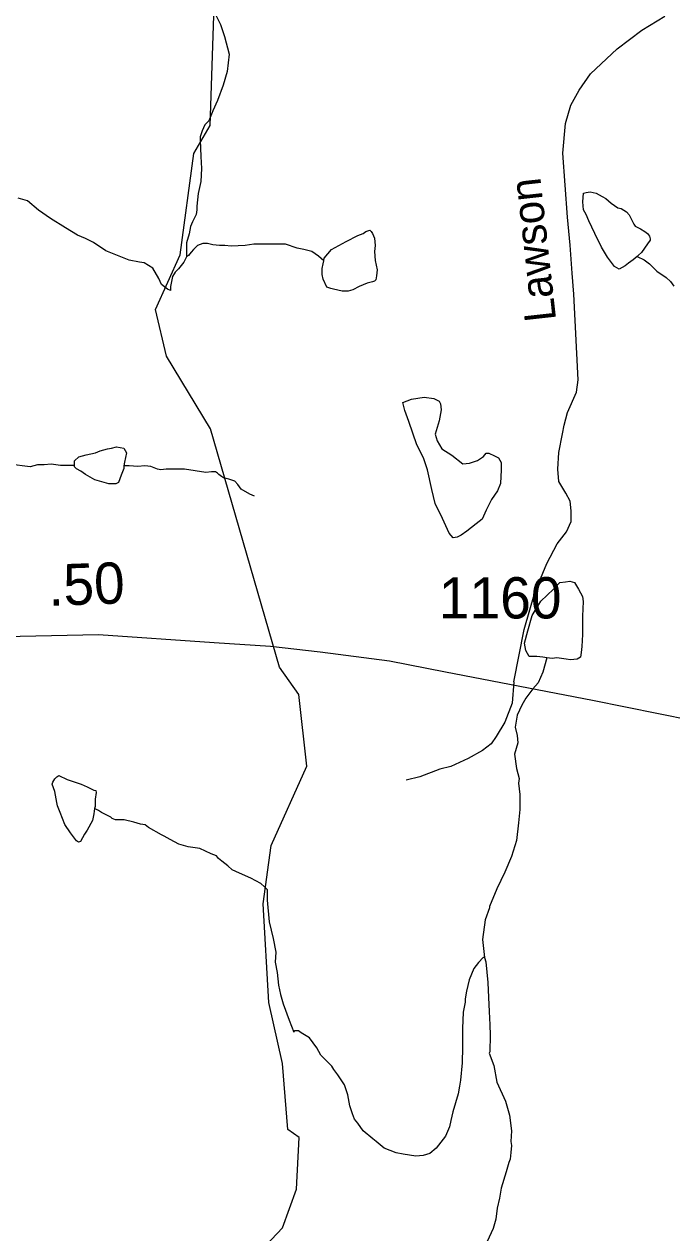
# Model space of a CAD drawing. Extents: x 2001466 to 2224147, y 644118 to 847247.
# Drawn here: x 2016789 to 2018752, y 719190 to 722853 of the extents above; entities that cross this region are included whole.
import ezdxf

# ---------------------------------------------------------------- set-up
doc = ezdxf.new("R2010")
doc.units = 0
for name, color, linetype in [('Exist Hydrographic Misc Water Feature', 7, 'Continuous'), ('Exist Road Non-System Type 51', 7, 'Continuous'), ('Exist Road Non-System Type 51 Label', 7, 'Continuous'), ('Exist Road Secondary Mileage Hundredths English Label', 7, 'Continuous'), ('Exist Road Secondary Type 51 Attributed', 7, 'Continuous'), ('Exist Road Secondary Type 51 Number Label', 7, 'Continuous')]:
    doc.layers.add(name, color=color, linetype=linetype)

msp = doc.modelspace()

# ---------------------------------------------------------------- linework, layer by layer
at = {"layer": 'Exist Hydrographic Misc Water Feature'}
msp.add_line((2017588.2, 719502.9), (2017572.2, 719703.4), dxfattribs=at)
for points in [[(2017572.2, 719703.4), (2017530.2, 719888), (2017513.2, 720187), (2017538.2, 720363.7), (2017646.3, 720604.2), (2017621.3, 720821.3), (2017563.2, 720904.5), (2017354.3, 721627.3), (2017220.2, 721846.6), (2017187.2, 721988.4), (2017262.2, 722154.2), (2017303.2, 722461.7), (2017353.2, 722546.1), (2017370.3, 723060.9), (2017878.4, 724028.3), (2017977.2, 724180.4), (2018152.3, 724528), (2018185.4, 724694.7)], [(2017370.5, 722880.2), (2017384.4, 722852.1), (2017396.5, 722816.1), (2017410.5, 722762.1), (2017404.5, 722710.1), (2017392.6, 722668.1), (2017374.6, 722622.2), (2017360.6, 722590.1), (2017348.5, 722560.1), (2017336.6, 722548.1), (2017328.6, 722530.1), (2017322.7, 722512.1), (2017322.7, 722502.1), (2017324.7, 722452.1), (2017326.8, 722416.1), (2017324.7, 722376.1), (2017316.7, 722340.2), (2017312.6, 722302.1), (2017312.6, 722290.1), (2017310.8, 722276.1), (2017298.9, 722254.1), (2017293, 722240.1), (2017288.9, 722218.1), (2017280.9, 722190.2), (2017280.9, 722160.1), (2017280.9, 722148.1)], [(2018646.7, 722148.9), (2018634.8, 722138.9), (2018620.7, 722128.9), (2018610.6, 722120.9), (2018592.8, 722110.9), (2018578.6, 722118.9), (2018556.7, 722146.9), (2018538.7, 722176.9), (2018518.8, 722218.8), (2018500.5, 722256.9), (2018492.5, 722276.8), (2018484.5, 722290.8), (2018482.7, 722314.8), (2018484.5, 722340.8), (2018492.5, 722342.8), (2018504.6, 722344.8), (2018522.7, 722340.8), (2018540.7, 722330.8), (2018552.6, 722324.8), (2018568.6, 722310.9), (2018588.7, 722296.9), (2018598.5, 722294.9), (2018614.5, 722284.9), (2018622.5, 722274.9), (2018636.7, 722247), (2018640.6, 722240.9), (2018656.8, 722233), (2018670.5, 722225), (2018678.7, 722219), (2018684.7, 722211), (2018686.7, 722203), (2018686.7, 722199), (2018678.5, 722187), (2018660.7, 722161), (2018650.8, 722152.9), (2018646.7, 722148.9)], [(2017232.9, 722046.1), (2017223, 722050.1), (2017205, 722064), (2017196.8, 722082.1), (2017179, 722114.1), (2017152.9, 722130.1), (2017138.8, 722132.1), (2017106.8, 722138.1), (2017036.9, 722166), (2016998.9, 722192), (2016974.9, 722203.9), (2016950.9, 722213.9), (2016914.8, 722235.9), (2016868.9, 722263.9), (2016832.8, 722289.9), (2016798.8, 722317.8), (2016770.9, 722325.8)], [(2017696.9, 722136.4), (2017698.8, 722144.4), (2017720.9, 722170.4), (2017764.8, 722194.5), (2017800.7, 722212.5), (2017816.7, 722218.5), (2017824.7, 722224.5), (2017836.8, 722228.5), (2017840.7, 722224.5), (2017844.8, 722218.5), (2017850.7, 722204.5), (2017852.8, 722182.5), (2017850.9, 722164.5), (2017852.8, 722136.5), (2017858.9, 722108.4), (2017856.9, 722090.5), (2017854.8, 722078.5), (2017850.9, 722074.5), (2017844.8, 722072.5), (2017828.8, 722068.5), (2017804.8, 722058.5), (2017784.9, 722048.5), (2017770.9, 722044.5), (2017752.9, 722044.5), (2017726.9, 722050.4), (2017718.9, 722052.4), (2017706.8, 722056.4), (2017694.9, 722080.4), (2017692.8, 722094.4), (2017692.8, 722112.4), (2017694.9, 722126.4), (2017696.9, 722136.4)], [(2017696.9, 722136.4), (2017680.9, 722150.4), (2017660.8, 722164.4), (2017636.8, 722170.4), (2017616.9, 722174.3), (2017580.9, 722186.3), (2017542.9, 722186.3), (2017502.9, 722186.3), (2017484.9, 722186.3), (2017458.9, 722182.2), (2017416.8, 722180.3), (2017396.9, 722182.2), (2017380.9, 722182.2), (2017360.8, 722184.2), (2017344.8, 722188.2), (2017330.9, 722188.2), (2017314.9, 722182.1), (2017302.8, 722170.1), (2017294.8, 722162.1), (2017286.8, 722152.1), (2017280.9, 722148.1)], [(2017280.9, 722148.1), (2017272.9, 722132.1), (2017256.9, 722112.1), (2017246.8, 722102.1), (2017238.8, 722088.1), (2017232.9, 722058.2), (2017232.9, 722046.1)], [(2018646.7, 722148.9), (2018668.7, 722138.9), (2018684.7, 722126.9), (2018706.8, 722105), (2018734.7, 722085), (2018748.6, 722073), (2018758.7, 722059)], [(2017955.1, 721648.6), (2017943.2, 721682.6), (2017937, 721706.6), (2017962.9, 721716.6), (2018001, 721722.6), (2018030.9, 721718.6), (2018047.1, 721710.6), (2018051, 721702.6), (2018053.1, 721684.7), (2018047.1, 721650.7), (2018035, 721610.6), (2018041, 721590.6), (2018055.1, 721566.6), (2018085.1, 721546.7), (2018119.1, 721520.7), (2018139, 721522.7), (2018163, 721530.8), (2018181, 721542.8), (2018189, 721552.8), (2018197, 721552.8), (2018215.1, 721544.8), (2018227.2, 721538.8), (2018235.2, 721524.8), (2018235.2, 721502.8), (2018233.1, 721460.8), (2018223.3, 721438.8), (2018205.2, 721412.8), (2018189.2, 721380.8), (2018177.1, 721352.8), (2018159.3, 721338.8), (2018131.2, 721316.8), (2018113.2, 721304.7), (2018101.3, 721298.7), (2018089.2, 721296.7), (2018077.3, 721310.7), (2018057.2, 721354.7), (2018035.3, 721400.7), (2018025.2, 721442.6), (2018011.1, 721502.6), (2017999.2, 721538.7), (2017979.1, 721578.6), (2017955.1, 721648.6)], [(2016941.3, 721516), (2016921.2, 721516), (2016899.3, 721516), (2016871.2, 721519.9), (2016849.2, 721517.9), (2016837.3, 721517.9), (2016829.3, 721517.9), (2016807.2, 721511.9), (2016743.4, 721519.9), (2016677.4, 721529.9), (2016621.4, 721541.8), (2016579.2, 721563.8), (2016523.2, 721571.7), (2016495.3, 721577.7), (2016475.4, 721585.8), (2016449.4, 721583.8), (2016439.3, 721579.7), (2016407.3, 721577.7), (2016383.4, 721573.7), (2016359.4, 721569.7), (2016343.4, 721565.6), (2016331.3, 721553.6), (2016319.4, 721545.7)], [(2016941.3, 721516), (2016941.3, 721522), (2016941.3, 721530), (2016955.2, 721542), (2016977.2, 721548), (2017005.3, 721554.1), (2017019.2, 721560.1), (2017041.2, 721566.1), (2017053.3, 721568.1), (2017069.3, 721572.1), (2017091.2, 721568.1), (2017099.2, 721554.1), (2017093.2, 721526.1), (2017091.2, 721514.2)], [(2017091.2, 721514.2), (2017091.2, 721506.1), (2017083.2, 721486.1), (2017075.4, 721464.1), (2017067.2, 721460.1), (2017045.3, 721460.1), (2017003.4, 721472.1), (2016975.1, 721488.1), (2016961.2, 721498), (2016947.2, 721506), (2016941.3, 721512), (2016941.3, 721516)], [(2017487.1, 721422.4), (2017473.2, 721428.3), (2017447.2, 721444.3), (2017437.1, 721458.3), (2017427.3, 721468.3), (2017409.2, 721474.3), (2017393.2, 721478.3), (2017387.3, 721482.3), (2017379.3, 721488.3), (2017375.2, 721492.3), (2017369.2, 721496.3), (2017357.1, 721496.3), (2017339.3, 721494.3), (2017275.1, 721504.2), (2017237.2, 721504.2), (2017219.1, 721504.2), (2017203.2, 721502.2), (2017193.3, 721504.1), (2017173.2, 721512.2), (2017155.2, 721514.2), (2017133.2, 721512.2), (2017107.2, 721514.2), (2017091.2, 721514.2)], [(2018373.4, 720933), (2018361.5, 720934.9), (2018343.4, 720936.9), (2018329.5, 720936.9), (2018319.5, 720936.9), (2018309.4, 720954.9), (2018305.5, 720976.9), (2018315.4, 721014.9), (2018329.3, 721060.9), (2018355.3, 721104.9), (2018393.3, 721140.9), (2018413.2, 721160.9), (2018429.4, 721162.9), (2018443.3, 721164.9), (2018457.2, 721160.9), (2018469.3, 721141), (2018481.2, 721119), (2018483.3, 721103), (2018481.2, 721058.9), (2018481.2, 721028.9), (2018481.2, 721003), (2018479.4, 720967), (2018477.3, 720949), (2018475.5, 720935), (2018465.5, 720929), (2018445.4, 720927), (2018431.4, 720929), (2018403.5, 720933), (2018389.4, 720931), (2018373.4, 720933)], [(2018373.4, 720933), (2018361.5, 720888.9), (2018347.3, 720856.9), (2018331.3, 720839), (2018309.4, 720810.9), (2018297.5, 720788.9), (2018283.6, 720758.9), (2018277.6, 720722.9), (2018283.6, 720696.9), (2018285.6, 720674.9), (2018275.6, 720640.9), (2018281.5, 720596.9), (2018289.5, 720566.9), (2018287.5, 720552.9), (2018291.8, 720518.9), (2018291.8, 720472.9), (2018287.7, 720433), (2018281.7, 720378.9), (2018265.7, 720330.9), (2018245.8, 720282.9), (2018221.8, 720232.9), (2018199.7, 720178.9), (2018199.7, 720174.9), (2018186, 720138.9), (2018178, 720078.9), (2018181.9, 720042.9), (2018183.9, 720025)], [(2017001.8, 720476.2), (2016999.7, 720460.2), (2016995.8, 720440.2), (2016979.8, 720410.2), (2016971.9, 720398.2), (2016960, 720376.2), (2016954, 720374.1), (2016947.9, 720378.1), (2016929.8, 720402.1), (2016911.8, 720428.1), (2016897.8, 720464.1), (2016889.8, 720484.1), (2016887.8, 720494.1), (2016881.8, 720528.1), (2016873.8, 720550), (2016875.9, 720556), (2016881.8, 720566), (2016887.8, 720572.1), (2016893.7, 720576), (2016919.8, 720564.1), (2016961.8, 720550.1), (2016979.8, 720542.1), (2016999.7, 720532.1), (2017005.9, 720530.2), (2017007.7, 720524.2), (2017003.8, 720504.2), (2017003.8, 720482.2), (2017001.8, 720476.2)], [(2017525.9, 720230.5), (2017517.9, 720238.5), (2017506, 720248.5), (2017475.9, 720264.5), (2017441.8, 720280.5), (2017419.9, 720290.5), (2017405.9, 720302.4), (2017387.9, 720316.4), (2017377.9, 720324.4), (2017371.9, 720332.4), (2017355.7, 720338.4), (2017321.9, 720354.4), (2017285.8, 720360.4), (2017257.9, 720368.4), (2017231.9, 720382.3), (2017213.8, 720392.3), (2017205.8, 720396.3), (2017165.8, 720418.3), (2017155.8, 720426.2), (2017141.8, 720428.2), (2017121.7, 720434.2), (2017091.8, 720442.2), (2017065.8, 720442.2), (2017055.7, 720446.2), (2017051.8, 720450.2), (2017043.8, 720454.2), (2017035.8, 720458.2), (2017023.7, 720464.2), (2017013.9, 720470.2), (2017001.8, 720476.2)], [(2017525.9, 720230.5), (2017525.9, 720198.5), (2017531.8, 720132.5), (2017543.9, 720082.5), (2017551.9, 720040.5), (2017550.1, 720010.6), (2017556, 719978.6), (2017560.1, 719940.6), (2017566.1, 719912.6), (2017574.1, 719884.6), (2017592.1, 719834.6), (2017606.1, 719798.6)], [(2018183.9, 720025), (2018180, 720024.9), (2018165.9, 720009), (2018151.9, 719990.9), (2018138, 719956.9), (2018130, 719922.9), (2018126.1, 719898.9), (2018126.1, 719888.9), (2018124, 719878.9), (2018119.9, 719858.9), (2018118.1, 719808.9), (2018118.1, 719774.9), (2018118.1, 719742.9), (2018116.2, 719715), (2018116.2, 719704.9), (2018112.1, 719652.9), (2018108.3, 719635), (2018104.1, 719611), (2018088.2, 719556.9), (2018082.2, 719530.9), (2018078.1, 719510.9), (2018066.2, 719483), (2018052.3, 719464.9), (2018038.3, 719446.9), (2018018.2, 719430.9), (2017998.3, 719424.9), (2017976.2, 719422.9), (2017938.3, 719428.8), (2017916.3, 719432.8), (2017880.2, 719446.8), (2017856.2, 719466.8), (2017846.2, 719474.8), (2017816.3, 719498.7), (2017800.3, 719522.7), (2017790.2, 719534.7), (2017784.3, 719550.8), (2017776.1, 719574.8), (2017770.1, 719608.7), (2017760.1, 719638.7), (2017740.2, 719668.7), (2017728.1, 719684.7), (2017722.1, 719694.7), (2017706.1, 719710.7), (2017700.2, 719716.7), (2017688.1, 719728.7), (2017676.2, 719750.7), (2017654.3, 719780.6), (2017628.2, 719796.6), (2017620.2, 719802.6), (2017608.1, 719802.6), (2017606.1, 719798.6)], [(2018183.9, 720025), (2018188, 720011), (2018194, 719948.9), (2018196, 719903), (2018198.1, 719861), (2018200.1, 719820.9), (2018202, 719788.9), (2018200.1, 719739), (2018198.1, 719735), (2018212.2, 719696.9), (2018222.1, 719647), (2018248.1, 719589), (2018260.2, 719547), (2018266.1, 719499), (2018264.1, 719467), (2018266.3, 719455), (2018264.3, 719433.1), (2018262.2, 719413), (2018258.3, 719403.1), (2018250.4, 719375), (2018234.4, 719325), (2018230.3, 719295.1), (2018222.5, 719265), (2018218.4, 719231.1), (2018210.4, 719203), (2018186.4, 719151)], [(2016839.2, 718238.5), (2016997.1, 718304.3), (2017106.2, 718420.2), (2017422.1, 719047), (2017572.2, 719204.7), (2017614.1, 719321.9), (2017622.1, 719479.3), (2017588.2, 719502.9)]]:
    msp.add_lwpolyline(points, dxfattribs=at)
at = {"layer": 'Exist Road Non-System Type 51'}
for points in [[(2018273.4, 720859.9), (2018305, 721018.3), (2018337.1, 721130.4), (2018373.1, 721218.6), (2018405.1, 721278.7), (2018433.2, 721314.7), (2018447.1, 721346.1), (2018447.1, 721378.2), (2018444.5, 721407.8), (2018431.1, 721431.9), (2018409.6, 721466.8), (2018406.9, 721504.3), (2018409.6, 721555.3), (2018420.3, 721611.6), (2018425.7, 721638.4), (2018436.4, 721676), (2018463.2, 721737.7), (2018468.6, 721775.2), (2018455.2, 722035.3), (2018449.8, 722098.1), (2018444.5, 722183), (2018436.4, 722268.8), (2018421.8, 722462.3), (2018429.8, 722551.8), (2018445.8, 722607.9), (2018471.2, 722653.4), (2018505.9, 722702.8), (2018586.5, 722778.5), (2018661.6, 722834.8), (2018731.3, 722877.7)], [(2018273.4, 720859.9), (2018268, 720795), (2018246.3, 720738.1), (2018219.3, 720694.8), (2018204.9, 720671.6), (2018178.8, 720651.5), (2018134.8, 720627.6), (2018082.7, 720603.9), (2018048.7, 720595.8), (2017988.6, 720572), (2017946.6, 720562)]]:
    msp.add_lwpolyline(points, dxfattribs=at)
at = {"layer": 'Exist Road Secondary Type 51 Attributed'}
msp.add_lwpolyline([(2015622.9, 721186.4), (2015749.1, 721109.4), (2015948.5, 721023.2), (2016082.5, 720983.3), (2016309.1, 720983.3), (2016544.8, 720991.3), (2016729.9, 720997.7), (2017013.9, 721003.3), (2017364.9, 720979.3), (2017535.3, 720968.1), (2017686.2, 720951), (2017896.1, 720923.5), (2018066.6, 720890.6), (2018511.7, 720804), (2018911.8, 720723.9), (2019062.1, 720691.1), (2019163.1, 720667.5), (2019321.2, 720620.2), (2019979.2, 720377.7)], dxfattribs=at)

# ---------------------------------------------------------------- texts
at = {"layer": 'Exist Road Non-System Type 51 Label'}
msp.add_text('Lawson', height=95, rotation=96.3384, dxfattribs=at).set_placement((2018401.7, 721956.4))
at = {"layer": 'Exist Road Secondary Mileage Hundredths English Label'}
msp.add_text('.50', height=125, rotation=1.9765, dxfattribs=at).set_placement((2016863.5, 721090.2))
at = {"layer": 'Exist Road Secondary Type 51 Number Label'}
msp.add_text('1160', height=125, dxfattribs=at).set_placement((2018046, 721052.1))

doc.saveas('drawing.dxf')
